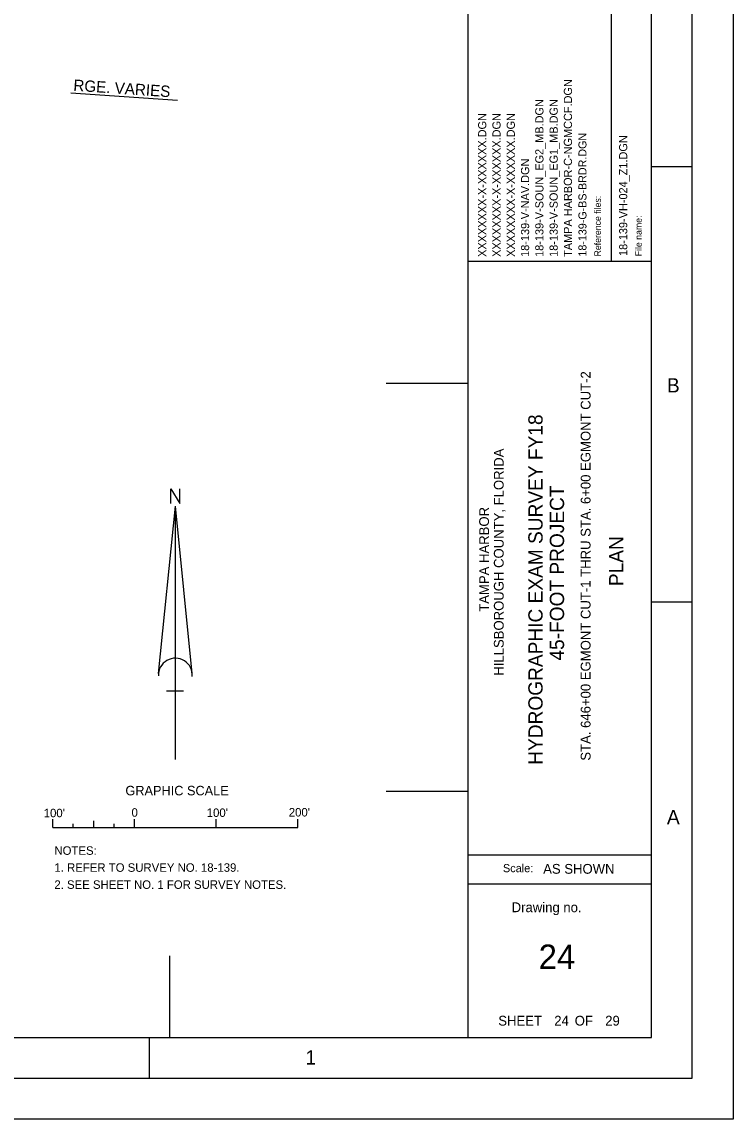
# Model space of a CAD drawing. Extents: x 401290 to 405690, y 1190598 to 1193998.
# Drawn here: x 404819 to 405690, y 1190598 to 1191942 of the extents above; entities that cross this region are included whole.
import ezdxf

# ---------------------------------------------------------------- set-up
doc = ezdxf.new("R2010")
doc.units = 0
for name, color, linetype in [('G-ANNO-NPLT', 7, 'Continuous'), ('G-ANNO-TEXT-DRWG', 7, 'Continuous'), ('G-ANNO-TEXT-PROJ', 7, 'Continuous'), ('G-ANNO-TEXT-TTLB', 7, 'Continuous'), ('G-ANNO-TTLB', 7, 'Continuous'), ('V-ALGN-TEXT', 7, 'Continuous'), ('V-ANNO-NOTE', 7, 'Continuous'), ('V-ANNO-SYMB', 7, 'Continuous'), ('V-TOPO-COOR-STAT', 7, 'Continuous')]:
    doc.layers.add(name, color=color, linetype=linetype)

msp = doc.modelspace()

# ---------------------------------------------------------------- linework, layer by layer
at = {"layer": 'G-ANNO-NPLT'}
msp.add_lwpolyline([(401290, 1193998.4), (405690, 1193998.4), (405690, 1190598.4), (401290, 1190598.4)], close=True, dxfattribs=at)
msp.add_lwpolyline([(405690, 1190648.4), (405690, 1190598.4), (405640, 1190598.4)], dxfattribs=at)
at = {"layer": 'G-ANNO-TTLB'}
for p, q in [((405365, 1193898.4), (405365, 1190698.4)), ((405540.7, 1192000.6), (405540.7, 1191649.2)), ((405640, 1191765), (405590, 1191765)), ((405365, 1191649.2), (405590, 1191649.2)), ((405640, 1191231.7), (405590, 1191231.7)), ((405365, 1190922.2), (405590, 1190922.2)), ((405365, 1190886.5), (405590, 1190886.5)), ((404975, 1190648.4), (404975, 1190698.4))]:
    msp.add_line(p, q, dxfattribs=at)
for points in [[(401340, 1190648.4), (405640, 1190648.4), (405640, 1193948.4), (401340, 1193948.4)], [(405590, 1193898.4), (401465, 1193898.4), (401465, 1190698.4), (405590, 1190698.4)]]:
    msp.add_lwpolyline(points, close=True, dxfattribs=at)
at = {"layer": 'V-ALGN-TEXT'}
msp.add_line((404878.7, 1191855.4), (405009.3, 1191846.6), dxfattribs=at)
at = {"layer": 'V-ANNO-NOTE'}
for p, q in [((404856.8, 1190955.4), (404856.8, 1190965.8)), ((404881.8, 1190955.4), (404881.8, 1190960.1)), ((404906.8, 1190955.4), (404906.8, 1190963.9)), ((404931.8, 1190955.4), (404931.8, 1190960.1)), ((404956.8, 1190955.4), (404956.8, 1190965.8)), ((404956.8, 1190955.4), (404956.8, 1190965.8)), ((404956.8, 1190955.4), (404956.8, 1190960.4)), ((405056.8, 1190955.4), (405056.8, 1190965.8)), ((405156.8, 1190955.4), (405156.8, 1190965.8)), ((404856.8, 1190955.4), (405156.8, 1190955.4))]:
    msp.add_line(p, q, dxfattribs=at)
at = {"layer": 'V-ANNO-SYMB'}
for p, q in [((404986.2, 1191144.3), (405006.8, 1191349.1)), ((405006.8, 1191038.8), (405006.8, 1191349.1)), ((405027.4, 1191144.3), (405006.8, 1191349.1)), ((405016.6, 1191122.6), (404995.9, 1191122.6))]:
    msp.add_line(p, q, dxfattribs=at)
msp.add_lwpolyline([(405001.1, 1191352.4), (405001.1, 1191370.5), (405012.4, 1191352.4), (405012.4, 1191370.5)], dxfattribs=at)
msp.add_arc((405006.8, 1191142.2), 20.7, 355.2984, 182.0673, dxfattribs=at)
at = {"layer": 'V-TOPO-COOR-STAT'}
for p, q in [((405265, 1191500), (405365, 1191500)), ((405265, 1191000), (405365, 1191000)), ((405000, 1190698.4), (405000, 1190798.4))]:
    msp.add_line(p, q, dxfattribs=at)

# ---------------------------------------------------------------- texts
at = {"layer": 'G-ANNO-TEXT-DRWG'}
for s, height, p in [('TAMPA HARBOR-C-NGMCCF.DGN', 10, (405492.7, 1191654.5)), ('18-139-V-SOUN_EG2_MB.DGN', 10, (405457.7, 1191654.5)), ('18-139-V-SOUN_EG1_MB.DGN', 10, (405475.2, 1191654.5)), ('XXXXXXXX-X-XXXXXX.DGN', 10, (405387.7, 1191654.5)), ('XXXXXXXX-X-XXXXXX.DGN', 10, (405405.2, 1191654.5)), ('XXXXXXXX-X-XXXXXX.DGN', 10, (405422.7, 1191654.5)), ('18-139-VH-024_Z1.DGN', 10, (405560.4, 1191655.6)), ('18-139-V-NAV.DGN', 10, (405440.2, 1191654.5)), ('STA. 646+00 EGMONT CUT-1 THRU STA. 6+00 EGMONT CUT-2', 12, (405515.4, 1191037.4)), ('PLAN', 17.5, (405555.6, 1191251.2))]:
    msp.add_text(s, height=height, rotation=90, dxfattribs=at).set_placement(p)
for s, height, p in [('24', 30, (405451.9, 1190782.2)), (' 24          29', 12, (405466.5, 1190712.9))]:
    msp.add_text(s, height=height, dxfattribs=at).set_placement(p)
at = {"layer": 'G-ANNO-TEXT-PROJ'}
for s, height, p in [('18-139-G-BS-BRDR.DGN', 9.8, (405510.4, 1191654.9)), ('HYDROGRAPHIC EXAM SURVEY FY18', 17.5, (405456.7, 1191032.4)), ('HILLSBOROUGH COUNTY, FLORIDA', 12, (405409, 1191141.5)), ('45-FOOT PROJECT', 17.5, (405483, 1191160)), ('TAMPA HARBOR', 12, (405391, 1191219.8))]:
    msp.add_text(s, height=height, rotation=90, dxfattribs=at).set_placement(p)
at = {"layer": 'G-ANNO-TEXT-TTLB'}
for s, p in [('Reference files:', (405528.1, 1191655)), ('File name:', (405578.1, 1191655.2))]:
    msp.add_text(s, height=8, rotation=90, dxfattribs=at).set_placement(p)
for s, height, p in [('Scale:', 10, (405408.1, 1190900.8)), ('AS SHOWN', 12, (405457.4, 1190898.9)), ('Drawing no.', 12, (405418.8, 1190851.8)), ('SHEET         OF', 12, (405402.4, 1190712.9))]:
    msp.add_text(s, height=height, dxfattribs=at).set_placement(p)
at = {"layer": 'G-ANNO-TTLB'}
for s, p in [('B', (405609, 1191488.4)), ('A', (405609, 1190959.6)), ('1', (405166.1, 1190665.1))]:
    msp.add_text(s, height=17.5, dxfattribs=at).set_placement(p)
at = {"layer": 'V-ALGN-TEXT'}
msp.add_text('RGE. VARIES', height=13.92, rotation=356.1651, dxfattribs=at).set_placement((404881.5, 1191858))
at = {"layer": 'V-ANNO-NOTE'}
for s, height, p in [('GRAPHIC SCALE', 11.666, (404945.6, 1190994.9)), ("100'", 10.42, (404845.5, 1190968.1)), ('0', 10.4, (404953.1, 1190968.8)), ("100'", 10.42, (405045.2, 1190968.5)), ("200'", 10.42, (405145.7, 1190969)), ('NOTES:', 10.42, (404858.6, 1190922.1)), ('1. REFER TO SURVEY NO. 18-139.', 10.416, (404858.6, 1190901.3)), ('2. SEE SHEET NO. 1 FOR SURVEY NOTES.', 10.416, (404858.6, 1190880.4))]:
    msp.add_text(s, height=height, dxfattribs=at).set_placement(p)

doc.saveas('drawing.dxf')
